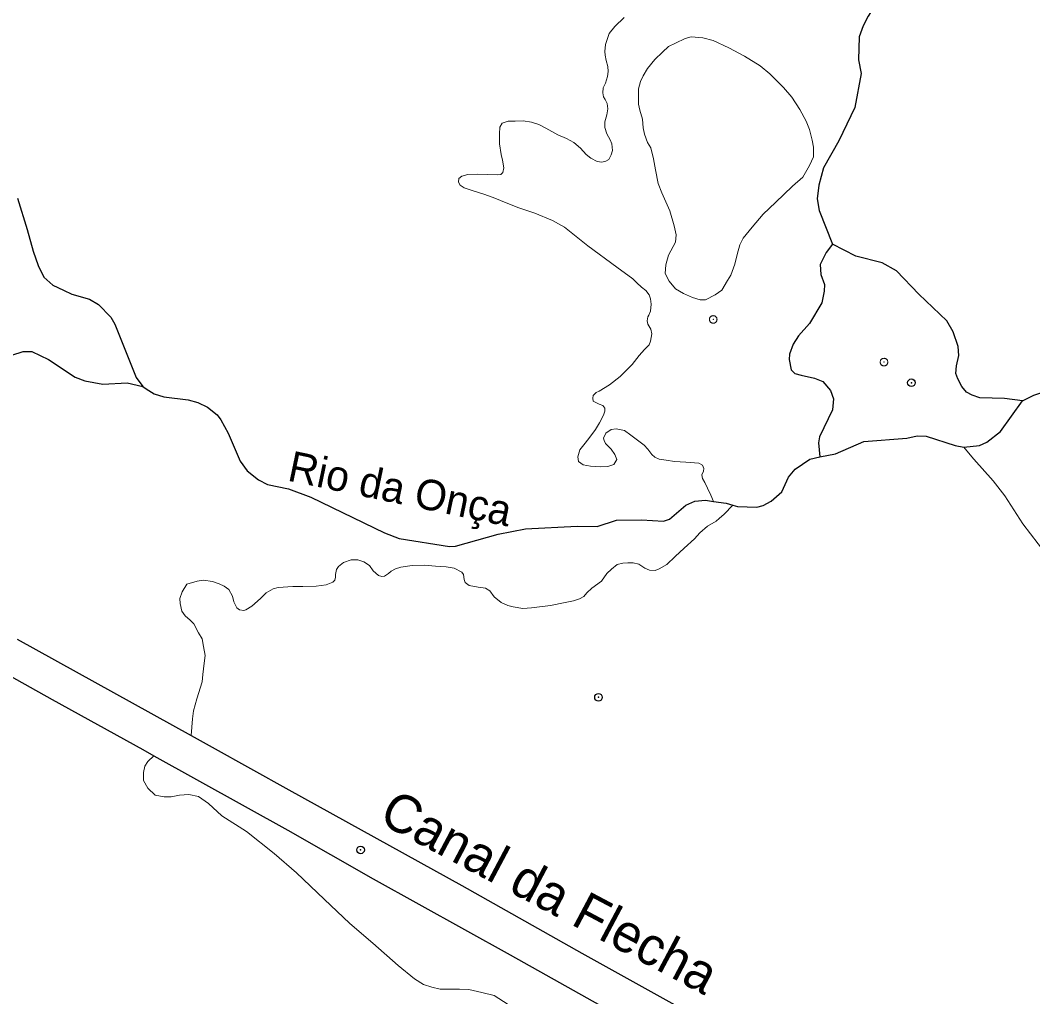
# Model space of a CAD drawing. Extents: x 267.7 to 296, y 7537.7 to 7565.8.
# Drawn here: x 273.164 to 275.825, y 7558.797 to 7561.365 of the extents above; entities that cross this region are included whole.
import ezdxf
from ezdxf.enums import TextEntityAlignment as Align

# ---------------------------------------------------------------- set-up
doc = ezdxf.new("R2010")
doc.units = 0
doc.header["$LTSCALE"] = 0.04
doc.header["$PDMODE"] = 32
doc.header["$PDSIZE"] = 0.02
doc.linetypes.add('SHORT_DASHED', pattern=[2.7, 1.5, -1.2])
for name, color, linetype, lineweight in [('1', 7, 'Continuous', 25), ('21', 7, 'SHORT_DASHED', 13), ('7', 7, 'Continuous', 25)]:
    doc.layers.add(name, color=color, linetype=linetype, lineweight=lineweight)
doc.layers.add('54', color=7, linetype='Continuous')
doc.layers.add('61', color=7, linetype='Continuous')

msp = doc.modelspace()

# ---------------------------------------------------------------- linework, layer by layer
at = {"layer": '1', "lineweight": 13}
msp.add_lwpolyline([(276.3494, 7558.4938), (276.3404, 7558.6888), (276.3258, 7558.8824), (276.3086, 7559.1552), (276.3077, 7559.1752), (276.3058, 7559.1852), (276.3013, 7559.1961), (276.2786, 7559.2252), (276.2413, 7559.2925), (276.2104, 7559.3479), (276.1176, 7559.5316), (276.0331, 7559.6907), (275.9658, 7559.8171), (275.9467, 7559.848), (275.9094, 7559.8989), (275.8394, 7559.988), (275.7994, 7560.0407), (275.7521, 7560.1144), (275.7212, 7560.1535), (275.6703, 7560.2107), (275.6567, 7560.2271), (275.6444, 7560.2424)], dxfattribs=at)
at = {"layer": '1'}
for points in [[(271.7705, 7560.2336), (272.0523, 7560.1585), (272.3601, 7560.0661), (272.4084, 7560.0478), (272.4492, 7560.0279), (272.5232, 7559.9829), (272.9143, 7559.7657), (273.248, 7559.5785), (273.486, 7559.447), (273.5154, 7559.4307)], [(273.1559, 7559.7378), (273.6133, 7559.4845)], [(273.6133, 7559.4845), (273.6688, 7559.4538), (273.8698, 7559.3417), (274.3247, 7559.0896), (274.6406, 7558.9119), (275.1689, 7558.6183)], [(273.5154, 7559.4307), (273.8671, 7559.2348), (274.0918, 7559.1075), (274.4521, 7558.907), (274.7467, 7558.7414), (275.1353, 7558.525), (275.4365, 7558.3553), (275.8235, 7558.1381), (276.1655, 7557.9434), (276.4451, 7557.7853)]]:
    msp.add_lwpolyline(points, dxfattribs=at)
msp.add_point((274.0586, 7559.1834), dxfattribs=at)
at = {"layer": '21'}
for points in [[(274.4242, 7561.0662), (274.425, 7561.0837), (274.431, 7561.0944), (274.447, 7561.0997), (274.4646, 7561.0997), (274.4859, 7561.1005), (274.508, 7561.0966), (274.527, 7561.0906), (274.5453, 7561.0814), (274.5773, 7561.0639), (274.6001, 7561.054), (274.6192, 7561.0433), (274.6367, 7561.0289), (274.6519, 7561.0121), (274.6641, 7561.0022), (274.6801, 7560.9931), (274.693, 7560.9915), (274.7029, 7560.9946), (274.7113, 7560.9984), (274.7174, 7561.0106), (274.7205, 7561.022), (274.7189, 7561.0395), (274.7144, 7561.0502), (274.706, 7561.0662), (274.7007, 7561.0829), (274.7007, 7561.0974), (274.706, 7561.1157), (274.7083, 7561.1317), (274.7068, 7561.1462), (274.7014, 7561.1568), (274.6976, 7561.1637), (274.6953, 7561.1736), (274.6961, 7561.1873), (274.7022, 7561.1995), (274.7075, 7561.217), (274.7098, 7561.2299), (274.709, 7561.2436), (274.7045, 7561.2589), (274.7014, 7561.2726), (274.7007, 7561.2825), (274.7022, 7561.3015), (274.7121, 7561.3297), (274.7266, 7561.3487), (274.7517, 7561.3723)], [(274.4326, 7560.9649), (274.4349, 7560.9771), (274.4318, 7560.9969), (274.428, 7561.0121), (274.4242, 7561.0395), (274.4242, 7561.0662)], [(274.9862, 7560.0998), (274.9794, 7560.1165), (274.9703, 7560.1347), (274.9634, 7560.1492), (274.9573, 7560.1599), (274.9558, 7560.1698), (274.9596, 7560.1789), (274.9611, 7560.1865), (274.9573, 7560.1949), (274.9474, 7560.2002), (274.9139, 7560.2025), (274.8834, 7560.2048), (274.8621, 7560.2078), (274.8438, 7560.2109), (274.8317, 7560.2162), (274.824, 7560.2231), (274.8141, 7560.2368), (274.8042, 7560.2475), (274.7936, 7560.2551), (274.7692, 7560.2741), (274.7524, 7560.2863), (274.7304, 7560.2901), (274.7174, 7560.2886), (274.7037, 7560.2794), (274.6976, 7560.2657), (274.6991, 7560.2596), (274.7022, 7560.252), (274.7174, 7560.2368), (274.7273, 7560.2231), (274.7319, 7560.2101), (274.7243, 7560.1964), (274.7083, 7560.1911), (274.6892, 7560.1903), (274.6633, 7560.1919), (274.6435, 7560.1957), (274.6314, 7560.2048), (274.6298, 7560.217), (274.6352, 7560.2353), (274.6451, 7560.2482), (274.6588, 7560.265), (274.6763, 7560.2886), (274.6869, 7560.3061), (274.6976, 7560.3267), (274.7007, 7560.3366), (274.7007, 7560.3449), (274.6953, 7560.3518), (274.6854, 7560.3556), (274.6755, 7560.3602), (274.6702, 7560.3632), (274.6694, 7560.3708), (274.6702, 7560.3784), (274.6778, 7560.3861), (274.6854, 7560.3899), (274.7128, 7560.4066), (274.741, 7560.428), (274.7722, 7560.4599), (274.7905, 7560.4836), (274.805, 7560.4988), (274.8172, 7560.511), (274.821, 7560.5209), (274.824, 7560.5399), (274.8218, 7560.5529), (274.8134, 7560.5658), (274.8119, 7560.5742), (274.8141, 7560.5848), (274.8164, 7560.5894), (274.821, 7560.6001), (274.8225, 7560.6184), (274.821, 7560.6321), (274.8172, 7560.6427), (274.808, 7560.6542), (274.7974, 7560.6633), (274.7844, 7560.6747), (274.7745, 7560.6846), (274.7326, 7560.7158), (274.6557, 7560.7714), (274.5948, 7560.8209), (274.5628, 7560.8385), (274.5163, 7560.8575), (274.4745, 7560.8712), (274.4455, 7560.8826), (274.4074, 7560.8986), (274.3823, 7560.9078), (274.3518, 7560.9169), (274.3313, 7560.9238), (274.3206, 7560.9314), (274.316, 7560.939), (274.3168, 7560.9489), (274.3252, 7560.955), (274.3404, 7560.9596), (274.3671, 7560.9603), (274.3922, 7560.9588), (274.4181, 7560.958), (274.4272, 7560.9588), (274.4326, 7560.9649)], [(274.9095, 7559.9763), (274.9361, 7560.001), (274.9504, 7560.0172), (274.9703, 7560.0343), (274.9932, 7560.0476), (275.0008, 7560.0543), (275.0141, 7560.0657), (275.0374, 7560.0898)], [(274.8182, 7559.9193), (274.8334, 7559.9183), (274.8439, 7559.9221), (274.8639, 7559.9336), (274.8857, 7559.9545), (274.9095, 7559.9763)], [(273.6133, 7559.4845), (273.6166, 7559.5276), (273.6195, 7559.5486), (273.6281, 7559.5809), (273.6423, 7559.6256), (273.6442, 7559.6446), (273.648, 7559.674), (273.6499, 7559.6949), (273.6461, 7559.7178), (273.6423, 7559.7387), (273.6328, 7559.7539), (273.6204, 7559.7777), (273.6109, 7559.7872), (273.5976, 7559.7986), (273.5891, 7559.8109), (273.5843, 7559.8309), (273.5834, 7559.8442), (273.59, 7559.8623), (273.6024, 7559.8822), (273.629, 7559.8898), (273.6461, 7559.8927), (273.6699, 7559.8889), (273.687, 7559.8832), (273.7003, 7559.8765), (273.7127, 7559.868), (273.7222, 7559.8509), (273.726, 7559.8356), (273.7336, 7559.8195), (273.7402, 7559.8147), (273.7516, 7559.8128), (273.7573, 7559.8147), (273.7725, 7559.8242), (273.7954, 7559.8442), (273.8106, 7559.8594), (273.8286, 7559.8699), (273.8419, 7559.8737), (273.8809, 7559.8756), (273.9066, 7559.8756), (273.9418, 7559.8765), (273.9684, 7559.8803), (273.9855, 7559.887), (273.9912, 7559.8927), (273.9931, 7559.9003), (273.9931, 7559.9079), (273.995, 7559.9202), (274.0007, 7559.9288), (274.014, 7559.9393), (274.034, 7559.9459), (274.0511, 7559.9459), (274.0672, 7559.9412), (274.0825, 7559.9307), (274.092, 7559.9174), (274.1062, 7559.905), (274.1148, 7559.9022), (274.1214, 7559.9031), (274.1319, 7559.9098), (274.1395, 7559.9164), (274.1509, 7559.9221), (274.1642, 7559.9269), (274.1946, 7559.9307), (274.2269, 7559.9317), (274.2555, 7559.9298), (274.284, 7559.9279), (274.3049, 7559.924), (274.3249, 7559.9136), (274.3296, 7559.9079), (274.3306, 7559.8946), (274.3334, 7559.886), (274.3439, 7559.8784), (274.3676, 7559.8746), (274.3867, 7559.8718), (274.3981, 7559.8642), (274.4095, 7559.8489), (274.4285, 7559.8337), (274.4456, 7559.8261), (274.4598, 7559.8223), (274.4855, 7559.8185), (274.5083, 7559.8195), (274.5578, 7559.8261), (274.5967, 7559.8337), (274.6186, 7559.8385), (274.6338, 7559.8432), (274.6452, 7559.8499), (274.6538, 7559.8594), (274.6661, 7559.8718), (274.6918, 7559.8898), (274.7061, 7559.9098), (274.7184, 7559.9212), (274.7327, 7559.9336), (274.7479, 7559.9374), (274.7612, 7559.9383), (274.7755, 7559.9383), (274.7897, 7559.9345), (274.8059, 7559.924), (274.8182, 7559.9193)], [(274.4468, 7558.7767), (274.4099, 7558.8001), (274.3778, 7558.8087), (274.3433, 7558.8161), (274.3187, 7558.8173), (274.2879, 7558.8173), (274.2682, 7558.8173), (274.246, 7558.8223), (274.2238, 7558.8297), (274.2004, 7558.8445), (274.1573, 7558.879), (274.0907, 7558.9381), (274.0303, 7558.9899), (273.9626, 7559.0539), (273.8899, 7559.1229), (273.832, 7559.1735), (273.7593, 7559.2314), (273.6939, 7559.2733), (273.6594, 7559.3053), (273.6323, 7559.3238), (273.6077, 7559.3287), (273.583, 7559.3275), (273.5609, 7559.3226), (273.5424, 7559.3226), (273.519, 7559.3275), (273.4993, 7559.346), (273.4882, 7559.3657), (273.4882, 7559.3866), (273.4919, 7559.4039), (273.4993, 7559.4162), (273.5154, 7559.4307)]]:
    msp.add_lwpolyline(points, dxfattribs=at)
msp.add_lwpolyline([(274.9311, 7560.6355), (274.9078, 7560.6463), (274.8862, 7560.6589), (274.87, 7560.6787), (274.8592, 7560.6985), (274.861, 7560.7219), (274.8682, 7560.747), (274.8862, 7560.7812), (274.888, 7560.801), (274.8826, 7560.8244), (274.8718, 7560.864), (274.8502, 7560.9107), (274.8412, 7560.9359), (274.834, 7560.9719), (274.8286, 7561.0006), (274.8214, 7561.0294), (274.8124, 7561.0438), (274.8052, 7561.0654), (274.8017, 7561.0816), (274.7999, 7561.105), (274.7927, 7561.1283), (274.7891, 7561.1445), (274.7891, 7561.1661), (274.7891, 7561.1841), (274.7945, 7561.2039), (274.8017, 7561.2183), (274.8124, 7561.238), (274.8322, 7561.2614), (274.852, 7561.2812), (274.8682, 7561.2956), (274.8862, 7561.3046), (274.9114, 7561.3172), (274.9275, 7561.3208), (274.9581, 7561.319), (274.9851, 7561.3118), (275.0265, 7561.292), (275.0678, 7561.2704), (275.1092, 7561.2452), (275.1344, 7561.2237), (275.1704, 7561.1877), (275.1919, 7561.1625), (275.2135, 7561.1301), (275.2297, 7561.0996), (275.2387, 7561.078), (275.2459, 7561.0492), (275.2495, 7561.0312), (275.2495, 7561.006), (275.2387, 7560.9827), (275.2207, 7560.9521), (275.1937, 7560.9287), (275.1488, 7560.8855), (275.1164, 7560.855), (275.0876, 7560.8208), (275.0642, 7560.792), (275.0552, 7560.774), (275.0481, 7560.7488), (275.0427, 7560.7237), (275.0319, 7560.6949), (275.0229, 7560.6805), (275.0085, 7560.6553), (274.9905, 7560.6427), (274.9653, 7560.6301), (274.9509, 7560.6301)], close=True, dxfattribs=at)
for p in [(274.9855, 7560.5781), (275.4344, 7560.4659)]:
    msp.add_point(p, dxfattribs=at)
at = {"layer": '54'}
for p in [(275.5063, 7560.4117), (274.684, 7559.5845)]:
    msp.add_point(p, dxfattribs=at)
at = {"layer": '7'}
for points in [[(275.4381, 7561.4484), (275.4214, 7561.4267), (275.4073, 7561.399), (275.3927, 7561.376), (275.3793, 7561.3503), (275.3694, 7561.3213), (275.3673, 7561.2611), (275.3741, 7561.225), (275.3577, 7561.1355), (275.3153, 7561.0475), (275.2756, 7560.9765), (275.2629, 7560.9316), (275.2591, 7560.8949), (275.2636, 7560.8645), (275.2989, 7560.7764)], [(273.157, 7560.8968), (273.1826, 7560.8146), (273.1979, 7560.7576), (273.2112, 7560.7196), (273.226, 7560.6896), (273.2503, 7560.668), (273.2781, 7560.655), (273.2997, 7560.6448), (273.3466, 7560.6316), (273.3699, 7560.6177), (273.4025, 7560.5838), (273.4126, 7560.5654), (273.4685, 7560.4252), (273.4866, 7560.4022)], [(275.2989, 7560.7764), (275.2991, 7560.7759), (275.2824, 7560.7538), (275.2666, 7560.7226), (275.2687, 7560.6962), (275.2778, 7560.6701), (275.2774, 7560.6525), (275.2711, 7560.622), (275.2382, 7560.5674), (275.2096, 7560.5351), (275.196, 7560.5135), (275.1864, 7560.4867), (275.1854, 7560.4726), (275.1907, 7560.4457), (275.2004, 7560.4363), (275.2168, 7560.4312), (275.2518, 7560.4239), (275.2733, 7560.4152), (275.2941, 7560.3909), (275.302, 7560.369), (275.2993, 7560.3407), (275.2649, 7560.2692), (275.2624, 7560.2541), (275.2658, 7560.2166)], [(275.7981, 7560.3637), (275.7509, 7560.3705), (275.6859, 7560.3717), (275.6664, 7560.3789), (275.651, 7560.3871), (275.6387, 7560.4014), (275.6284, 7560.422), (275.6233, 7560.4363), (275.6253, 7560.4558), (275.6309, 7560.4832), (275.6296, 7560.5074), (275.6164, 7560.5459), (275.5999, 7560.5745), (275.5259, 7560.6443), (275.467, 7560.7057), (275.4294, 7560.7272), (275.3606, 7560.7445), (275.2989, 7560.7764)], [(273.1418, 7560.4838), (273.1717, 7560.494), (273.195, 7560.4942), (273.2388, 7560.4724), (273.3089, 7560.4263), (273.3342, 7560.4167), (273.3812, 7560.4081), (273.445, 7560.4112), (273.4866, 7560.4022)], [(273.4866, 7560.4022), (273.4955, 7560.3953), (273.5164, 7560.3829), (273.542, 7560.3744), (273.6058, 7560.3665), (273.6307, 7560.3595), (273.6562, 7560.3475), (273.6817, 7560.3277), (273.6916, 7560.3142), (273.7107, 7560.2787), (273.7419, 7560.2053), (273.7603, 7560.1797), (273.7903, 7560.1568), (273.8137, 7560.1444), (273.8696, 7560.1325), (273.9284, 7560.1106), (274.1213, 7560.017), (274.1598, 7560.0023), (274.2924, 7559.9814), (274.3078, 7559.9824), (274.4207, 7560.0136), (274.4919, 7560.0274), (274.6281, 7560.0344), (274.6807, 7560.0341), (274.7316, 7560.0501), (274.7968, 7560.0512), (274.8552, 7560.0481), (274.8703, 7560.053), (274.9134, 7560.0897), (274.9372, 7560.1004), (274.9653, 7560.1029), (274.9862, 7560.0998)], [(275.7981, 7560.3637), (275.7983, 7560.364), (275.8283, 7560.3791), (275.8814, 7560.3968), (275.92, 7560.4002), (275.9209, 7560.4005)], [(275.6444, 7560.2424), (275.6857, 7560.2465), (275.7047, 7560.2552), (275.7408, 7560.2832), (275.7981, 7560.3637)], [(275.2658, 7560.2166), (275.3068, 7560.2251), (275.3818, 7560.2574), (275.4946, 7560.2661), (275.5217, 7560.2725), (275.545, 7560.2711), (275.6212, 7560.2466), (275.6444, 7560.2424)], [(275.0374, 7560.0898), (275.0492, 7560.0864), (275.1004, 7560.0846), (275.1172, 7560.0889), (275.1381, 7560.1002), (275.1659, 7560.1251), (275.183, 7560.1634), (275.2005, 7560.1843), (275.2395, 7560.2111), (275.2658, 7560.2166)], [(274.9862, 7560.0998), (275.02, 7560.0949), (275.0374, 7560.0898)]]:
    msp.add_lwpolyline(points, dxfattribs=at)

# ---------------------------------------------------------------- texts
at = {"layer": '1'}
msp.add_text('Canal da Flecha', height=0.1, rotation=332.049, dxfattribs=at).set_placement((274.5329, 7559.0289), align=Align.CENTER)
at = {"layer": '61'}
msp.add_text('Rio da Onça', height=0.08, rotation=348.211, dxfattribs=at).set_placement((274.1548, 7560.0942), align=Align.CENTER)

doc.saveas('drawing.dxf')
